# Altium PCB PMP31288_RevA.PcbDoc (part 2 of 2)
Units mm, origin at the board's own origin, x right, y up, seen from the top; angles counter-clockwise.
Board outline 73.66 x 62.23 mm, 2 copper layers (Top Layer, Bottom Layer), stack 1.575 mm thick; 96 components, 44 nets, 195 pads, 25 vias.
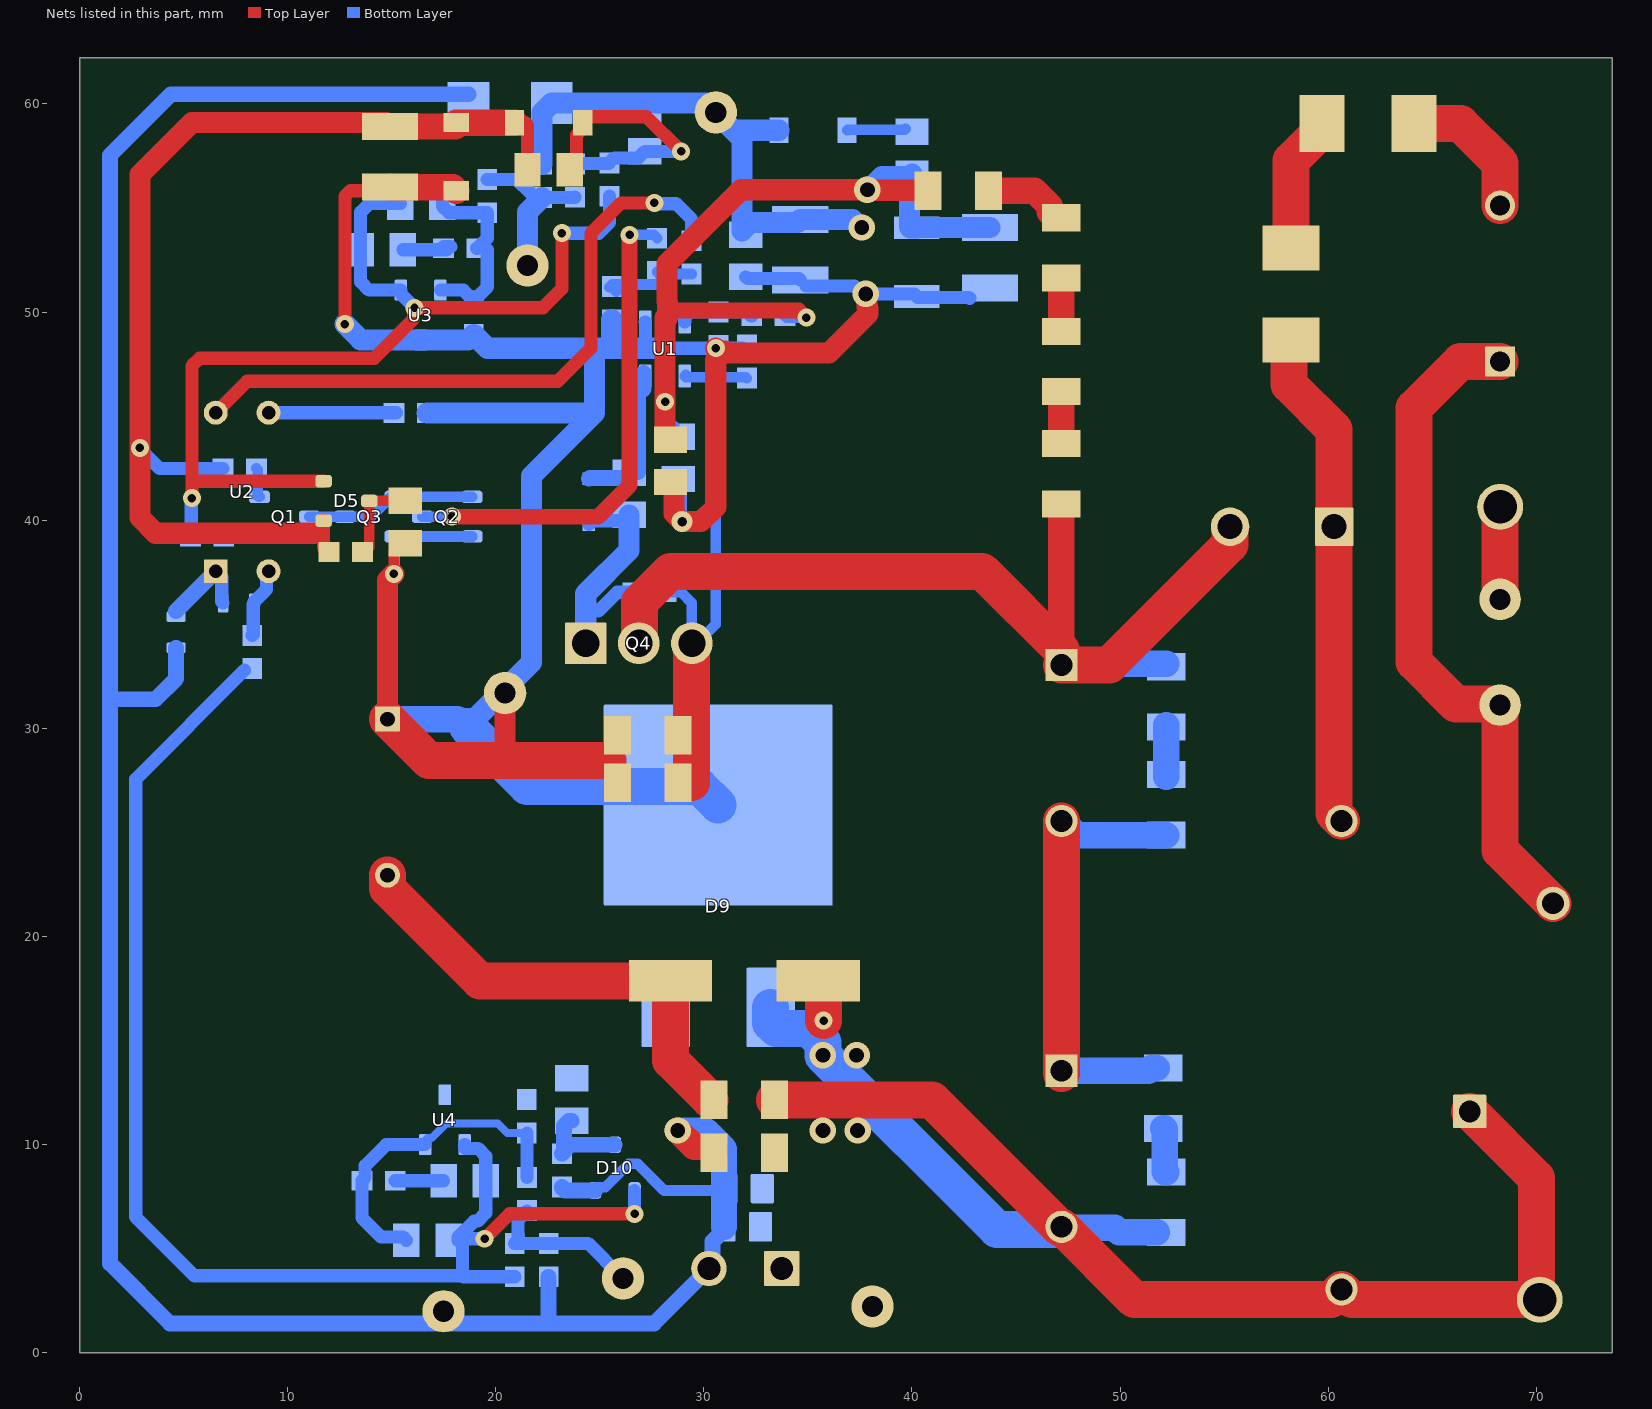
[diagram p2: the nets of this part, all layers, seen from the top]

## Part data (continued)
TP1 TP2 TP4 TP5 TP6: library part CMP-0055137-2, "Test Point, Miniature, Red, TH", Color=Red, Manufacturer="Keystone Electronics", Supplier Part Number 1=36-5000-ND
TP3: library part CMP-0055157-2, "Test Point, Multipurpose, Brown, TH", Color=Brown, Manufacturer="Keystone Electronics", Supplier Part Number 1=36-5125-ND
TP7: library part CMP-0055156-2, "Test Point, Multipurpose, Blue, TH", Color=Blue, Manufacturer="Keystone Electronics", Supplier Part Number 1=36-5127-ND
TP8: library part CMP-0055138-2, "Test Point, Miniature, Black, TH", Color=Black, Manufacturer="Keystone Electronics", Supplier Part Number 1=36-5001-ND
U1: library part CMP-0001574-1, "Continuous Conduction Mode (CCM) Secondary Side Regulated (SSR) Current-Mode Offline Flyback Controller", Manufacturer="Texas Instruments", Max Supply Voltage=29.7V, Min Supply Voltage=8V, Nominal Supply Current=1.8-2mA, Operating Temperature Range="-40°C to +125°C"
U2: library part CMP-0006173-3, "Optocoupler, 5 kV, 80-160% CTR, TH", Manufacturer="Fairchild Semiconductor", Supplier Part Number 1=FOD817A-ND, Voltage_Isolation_Vrms=5kV
U3 U4: library part CMP-0033157-1, "Adjustable Precision Shunt Regulator, 34 ppm / degC, 100 mA, -40 to 125 degC, 3-pin SOT-23 (DBZ), Green (RoHS & no Sb/Br)", Manufacturer="Texas Instruments", Rating=Catalog, Temp Coeff(Max)(ppm/ degree C)=92, Temp Coeff(Typ)(ppm/ degree C)=34
XF1: library part CMP-0003627-1, "Fuse Holder, TR5, TH", Manufacturer=Littelfuse, Supplier Part Number 1=WK6235-ND

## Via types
v1: diameter 0.864, hole 0.406, Top Layer to Bottom Layer, 14 vias
v2: diameter 1.27, hole 0.711, Top Layer to Bottom Layer, 8 vias
v3: diameter 0.864, hole 0.406, Top Layer to Bottom Layer, tented bottom, 2 vias
v4: diameter 1.016, hole 0.457, Top Layer to Bottom Layer, 1 vias

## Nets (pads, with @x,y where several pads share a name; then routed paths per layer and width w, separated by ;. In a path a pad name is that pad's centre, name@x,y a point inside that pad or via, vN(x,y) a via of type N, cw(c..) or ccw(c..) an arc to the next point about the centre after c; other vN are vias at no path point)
CS: Q4.3 R14.2 R27.2 R28.1 R31.2 | length 22
  Top Layer w1.778: 29.414,27.385 29.414,34.075 Q4.3@29.424,34.085
  Bottom Layer w0.508: R27.2@28.185,36.535 28.908,36.535 29.424,36.019 Q4.3@29.424,34.085 29.653,34.085 30.574,35.006 R14.2@30.574,45.398
DRV: D6.1 R26.2 U1.6 | length 6.9
  Bottom Layer w0.762: D6.1@24.476,41.992 24.514,42.029 26.154,42.029 R26.2@26.408,42.283 ; R26.2@26.849,42.309 26.849,46.063 27.103,46.317 U1.6@27.103,47.079
EA1: C14.2 C19.2 D10.1 R11.1 R34.1 U4.1 | length 65.8
  Top Layer w0.635: v1(19.467,5.469) 20.665,6.667 v3(26.67,6.667)
  Bottom Layer w0.635: R11.1@7.923,32.783 2.699,27.559 2.699,6.509 5.521,3.687 18.407,3.687 ; U4.1@18.506,9.992 18.506,9.827 18.524,9.81 19.15,9.81 19.522,9.438 C19.2@19.522,8.255 19.522,6.711 19.133,6.322 18.968,6.322 18.201,5.555 C14.2@18.201,5.39 ; v1(19.467,5.469) 18.28,5.469 C14.2@18.201,5.39 ; R34.1@20.908,3.645 18.449,3.645 18.407,3.687 ; D10.1@26.668,7.79 26.669,7.789 v3(26.67,6.667) v3(26.67,6.667) ; C14.2@18.201,5.39 18.407,5.184 18.407,3.687
FB: C9.1 R9.2 R21.2 U1.2 | length 7.1
  Bottom Layer w0.508: C9.1@25.465,51.193 25.597,51.325 28.134,51.325 U1.2@28.134,49.526 ; C9.1@25.575,51.228 25.575,51.203 C9.1@25.796,50.982 ; R21.2@27.753,51.946 27.753,51.921 28.229,51.445 ; R21.2@27.845,51.829 R9.2@29.408,51.829
NetC1_1: C1.1 C2.1 C6.1 C7.1 R1.2 R8.2 R12.2 U1.5 | length 42.1
  Top Layer w0.762: 28.253,50.078 34.548,50.078 34.898,49.729 v1(34.925,49.729)
  Top Layer w1.016: 28.134,49.729 v1(28.134,45.69) 28.134,43.994 28.261,43.867 C6.1@28.394,43.867 ; 28.253,49.729 28.253,50.078 28.253,50.478 28.228,50.502 28.228,52.322 31.786,55.88 v2(37.856,55.88) 37.881,55.855 40.753,55.855 R12.2@40.778,55.83
  Bottom Layer w0.508: U1.5@28.134,46.926 v1(28.134,45.69) 28.134,44.715 28.331,44.517 C7.1@28.57,44.517 ; R8.2@33.899,49.806 33.977,49.729 v1(34.925,49.729) ; v2(37.856,55.88) v2@37.856,55.891
  Bottom Layer w1.016: v2(37.856,55.88) 37.925,55.88 38.56,56.515 39.878,56.515 R1.2@40.005,56.642 ; R1.2@39.877,56.558 39.877,54.095 39.92,54.053 C2.1@40.234,54.053 40.239,54.058 43.751,54.058 C1.1@43.756,54.064
NetC3_1: C3.1 D3.1 D4.1 D5.2 R4.2 R15.2 R16.2 | length 54
  Top Layer w0.635: 11.256,39.37 11.646,39.759 11.646,39.957 11.663,39.975 D5.2@11.728,39.975 11.728,38.735 ccw(c11.993,38.735) R16.2@11.993,38.47 ; C3.1@14.735,59.105 C3.1@14.922,58.917 ; D3.1@20.905,59.105 21.339,59.105 cw(c21.339,58.917) 21.526,58.917 R4.2@21.526,56.832
  Top Layer w1.016: 11.256,39.37 3.651,39.37 2.897,40.125 v1(2.897,43.473) 2.897,56.603 5.399,59.105 C3.1@14.735,59.105
  Top Layer w1.27: C3.1@14.922,58.917 D4.1@18.063,58.917 ; D4.1@18.098,59.105 D3.1@20.905,59.105
  Bottom Layer w0.635: v1(2.897,43.473) 2.897,43.429 3.841,42.485 R15.2@6.896,42.485
NetC4_1: C4.1 C5.1 D1.2 D2.1 R2.2 R3.1 TP1.1 | length 25.7
  Bottom Layer w1.016: R2.2@22.225,57.099 22.225,59.578 D2.1@22.691,60.045 30.125,60.045 TP1.1@30.574,59.596 31.432,58.737 ; D1.2@33.605,58.737 31.432,58.737 ; v2(37.586,54.064) 37.517,54.064 37.137,54.443 34.631,54.443 C4.1@34.63,54.445 34.488,54.303 32.242,54.303 31.84,53.9 31.84,58.33 31.432,58.737
NetC8_1: C8.1 R13.1 R19.1 R24.2 U3.2 | length 9
  Bottom Layer w0.635: U3.2@17.342,51.056 18.438,51.056 R24.2@18.941,50.554 ; C8.1@17.438,55.379 C8.1@17.438,55.214 17.438,55.086 17.755,54.769 R13.1@19.589,54.769 19.589,53.543 19.114,53.069 R19.1@19.089,53.069 ; R24.2@18.941,50.529 R24.2@18.941,50.554 ; R19.1@19.589,52.995 19.589,51.201 R24.2@18.941,50.554
NetC8_2: C8.2 C11.2 D5.1 R7.1 R20.1 U3.1 | length 49.2
  Top Layer w0.635: v1(5.399,41.059) 5.399,41.875 ; D5.1@11.728,41.875 5.399,41.875 ; v1(23.177,53.789) 23.177,51.117 22.264,50.204 v1(16.094,50.204) 16.05,50.16 16.05,49.671 14.163,47.784 5.771,47.784 5.399,47.412 5.399,41.875
  Bottom Layer w0.635: R20.1@5.328,39.217 5.363,39.252 5.363,41.024 v1(5.399,41.059) ; C8.2@15.406,55.214 13.924,55.214 13.506,54.796 C11.2@13.506,52.995 13.506,51.459 13.908,51.056 U3.1@15.442,51.056 15.442,50.891 16.094,50.239 v1(16.094,50.204) ; v1(23.177,53.789) 24.951,53.789 25.465,54.303 R7.1@25.465,55.569
NetC10_1: C10.1 R14.1 U1.4 | length 3
  Bottom Layer w0.508: U1.4@29.084,46.926 29.084,46.921 29.13,46.875 32.017,46.875 C10.1@32.067,46.825 ; U1.4@29.128,46.992 U1.4@29.13,46.991
NetC11_1: C11.1 R19.2 | length 2.5
  Bottom Layer w0.635: C11.1@15.538,52.995 R19.2@17.638,52.995 ; R19.2@17.489,53.143 R19.2@17.84,53.143
NetC12_1: C12.1 D5.3 R16.1 | length 4.4
  Top Layer w0.508: R16.1@13.593,38.47 ccw(c13.593,38.806) 13.928,38.806 D5.3@13.928,40.925 C12.1@15.65,40.925
  Top Layer w1.016: C12.1@15.65,40.925 C12.1@15.65,40.927
NetC13_1: C13.1 L1.2 Q4.2 R25.1 R32.2 | length 48.6
  Top Layer w1.27: C13.1@47.184,33.04 47.184,33.735 R25.1@47.184,40.778
  Top Layer w1.778: Q4.2@26.874,34.085 26.916,34.128 26.916,36.067 28.394,37.545 43.374,37.545 C13.1@47.184,33.735 ; C13.1@47.184,33.04 49.484,33.04 55.271,38.827 55.271,39.674 L1.2@55.285,39.688
  Bottom Layer w1.27: C13.1@47.184,33.04 47.252,33.108 R32.2@52.229,33.108
NetC13_2: C13.2 C20.1 R33.1 R41.2 | length 22.1
  Top Layer w1.778: C20.1@47.184,13.415 C20.1@47.184,13.545 C13.2@47.184,25.54
  Bottom Layer w1.27: C13.2@47.184,25.54 47.259,25.54 47.939,24.86 R33.1@52.229,24.86 ; C20.1@47.197,13.558 C20.1@47.184,13.545 51.348,13.545 51.478,13.674 R41.2@51.752,13.674
NetC14_1: C14.1 R35.1 R40.1 R43.2 U4.2 | length 16.2
  Bottom Layer w0.381: U4.2@16.606,9.992 16.606,10.192 16.716,10.302 16.916,10.302 17.625,11.011 20.094,11.011 20.551,10.553 R43.2@21.497,10.553
  Bottom Layer w0.635: C14.1@15.7,5.402 15.543,5.559 14.484,5.559 13.571,6.472 R40.1@13.571,8.255 13.723,8.407 13.723,8.98 14.735,9.992 U4.2@16.606,9.992 ; R43.2@21.497,10.553 21.497,8.424 R35.1@21.501,8.42
NetC15_1: C15.1 D8.1 L1.1 | length 24.2
  Top Layer w1.778: D8.1@58.219,48.662 58.114,48.556 58.114,46.521 60.285,44.35 L1.1@60.285,39.688 60.285,25.895 C15.1@60.642,25.538
NetC19_1: C19.1 R40.2 | length 2.3
  Bottom Layer w0.635: R40.2@15.171,8.255 C19.1@17.49,8.255
NetC21_1: C21.1 D10.3 R36.1 | length 4.4
  Bottom Layer w0.762: R36.1@23.177,9.552 23.272,9.646 R36.1@23.272,9.671 ; C21.1@23.652,11.141 23.526,11.141 23.272,10.887 R36.1@23.272,9.671 ; D10.3@25.717,9.99 23.591,9.99 R36.1@23.272,9.671
NetD1_1: D1.1 R1.1 | length 2.8
  Bottom Layer w0.508: D1.1@36.88,58.737 36.912,58.769 39.656,58.769 R1.1@39.688,58.801
NetD3_2: D3.2 R3.2 R4.1 R5.2 R7.2 | length 13.6
  Top Layer w0.635: R4.1@23.558,56.832 23.876,57.15 23.876,58.498 24.04,58.663 24.04,58.812 24.105,58.877 24.255,58.877 24.255,59.323 24.32,59.388 27.242,59.388 v1(28.908,57.721)
  Bottom Layer w0.635: R5.2@23.812,57.121 23.836,57.145 25.441,57.145 R7.2@25.465,57.169 25.465,57.194 25.623,57.351 25.648,57.351 25.7,57.404 26.849,57.404 R3.2@27.166,57.721 v1(28.908,57.721)
NetD6_2: D6.2 Q4.1 R26.1 R27.1 | length 11.8
  Bottom Layer w0.635: 24.324,35.64 24.939,35.64 25.834,36.535 R27.1@26.584,36.535 ; 24.324,36.462 24.397,36.535 ; D6.2@24.476,39.792 24.656,39.971 26.128,39.971 R26.1@26.408,40.251
  Bottom Layer w1.016: Q4.1@24.324,34.085 24.324,35.64 24.324,36.462 ; 24.397,36.535 26.408,38.546 R26.1@26.408,40.251
NetD7_1: D7.1 D8.2 | length 6.6
  Top Layer w1.778: D8.2@58.219,53.082 58.219,57.28 59.702,58.763 D7.1@59.702,59.055
NetD7_2: D7.2 R29.2 | length 7
  Top Layer w1.778: D7.2@64.123,59.055 66.358,59.055 68.263,57.15 R29.2@68.263,55.125
NetQ1_1: Q1.1 R20.2 | length 1.7
  Bottom Layer w0.508: R20.2@6.928,39.217 Q1.1@8.646,39.217
NetQ1_2: Q1.2 R15.1 | length 1.4
  Bottom Layer w0.508: R15.1@8.496,42.485 8.571,42.41 8.571,41.163 8.617,41.117 Q1.2@8.646,41.117
NetQ1_3: Q1.3 Q2.1 Q3.1 Q3.3 | length 8.2
  Bottom Layer w0.508: Q1.3@11.046,40.167 Q3.3@12.75,40.167 14.012,40.167 14.904,41.059 14.904,41.071 14.95,41.117 Q3.1@15.15,41.117 Q2.1@18.866,41.117
NetQ2_3: Q2.3 R21.1 | length 24
  Top Layer w0.762: v1@17.886,40.164 24.922,40.164 26.434,41.675 v1(26.434,53.706)
  Bottom Layer w0.508: Q2.3@16.466,40.167 v1(17.886,40.167) ; v1(26.434,53.706) 27.593,53.706 R21.1@27.753,53.546
NetR2_1: R2.1 R5.1 R13.2 TP2.1 | length 7.5
  Bottom Layer w0.635: R13.2@19.589,56.369 21.016,56.369 21.704,55.681 ; R2.1@22.225,55.499 22.236,55.51 23.801,55.51 R5.1@23.812,55.521
  Bottom Layer w1.016: TP2.1@21.526,52.236 21.526,54.8 R2.1@22.225,55.499
NetR6_1: R6.1 R10.2 U2.1 | length 4.4
  Bottom Layer w0.635: U2.1@6.544,37.545 6.829,37.259 6.829,36.086 R10.2@6.896,36.019
  Bottom Layer w0.762: 4.639,35.64 U2.1@6.544,37.545
NetR8_1: R8.1 R22.2 U1.3 | length 3.6
  Bottom Layer w0.635: U1.3@29.084,49.526 29.084,49.741 29.348,50.006 30.695,50.006 R22.2@30.697,50.003 32.077,50.003 32.274,49.806 R8.1@32.299,49.806
NetR9_1: R9.1 U2.4 | length 31.8
  Top Layer w0.635: U2.4@6.544,45.165 8.052,46.672 22.982,46.672 24.573,48.263 24.573,53.789 26.029,55.245 v3(27.622,55.245)
  Bottom Layer w0.635: U2.4@6.544,45.165 U2.4@6.544,45.304 ; v3(27.622,55.245) 27.666,55.201 28.667,55.201 29.408,54.46 R9.1@29.408,53.429
NetR10_1: R10.1 R11.2 U2.2 | length 3.4
  Bottom Layer w0.635: R11.2@8.303,34.465 8.35,34.512 8.35,35.972 R10.1@8.396,36.019 8.396,36.084 8.985,36.673 8.985,37.446 U2.2@9.084,37.545
NetR12_1: R12.1 R17.2 | length 4.2
  Top Layer w1.27: R12.1@43.677,55.83 45.885,55.83 46.629,55.086 46.629,54.811 46.909,54.532 R17.2@47.184,54.532
NetR17_1: R17.1 R23.2 | length 2.6
  Top Layer w1.27: R23.2@47.184,49.075 R17.1@47.184,51.632
NetR18_2: R18.2 U2.3 | length 6.1
  Bottom Layer w0.635: U2.3@9.084,45.165 R18.2@15.221,45.165
NetR23_1: R23.1 R25.2 | length 2.5
  Top Layer w1.27: R25.2@47.184,43.677 R23.1@47.184,46.175
NetR29_1: R29.1 R37.2 XF1.1 | length 32.8
  Top Layer w1.778: R29.1@68.263,47.625 66.358,47.625 64.123,45.39 64.123,33.181 66.146,31.157 68.22,31.157 XF1.1@68.263,31.115 68.263,24.13 R37.2@70.802,21.59
NetR30_1: R30.1 R34.2 R35.2 TP6.1 | length 8
  Bottom Layer w0.635: R35.2@21.683,6.638 21.658,6.638 21.501,6.795 21.065,6.36 21.065,5.402 R34.2@20.908,5.245 R30.1@22.543,5.245 24.439,5.245 26.039,3.644 26.039,3.568 TP6.1@26.116,3.568
NetR32_1: R32.1 R33.2 | length 2.5
  Bottom Layer w1.27: R33.2@52.229,27.674 R32.1@52.229,30.137
NetR41_1: R41.1 R42.2 | length 2.2
  Bottom Layer w1.27: R41.1@52.07,10.774 52.134,10.774 52.149,10.759 52.149,8.69 52.164,8.675 R42.2@52.229,8.675
NetTP3_1: TP3.1 XF1.2 | length 4.4
  Top Layer w1.778: XF1.2@68.263,36.195 TP3.1@68.263,40.64
PGND: C15.2 C16.2 C17.2 C18.2 C20.2 C21.2 D9.1 D9.3 J1.1 R37.1 R38.1 R39.1 R42.1 R43.1 TP7.1 TP8.1 U4.3 | length 77.5
  Top Layer w1.778: C17.2@33.394,12.145 40.954,12.145 C20.2@47.119,5.98 ; C18.2@35.494,17.86 35.643,17.86 35.754,17.749 v1(35.754,15.955) ; C20.2@47.184,6.045 50.688,2.54 60.145,2.54 C15.2@60.642,3.037 61.14,2.54 TP7.1@70.168,2.54 70.168,2.657 70.009,2.816 70.009,8.384 R37.1@66.802,11.59
  Bottom Layer w1.27: C20.2@47.184,6.045 47.237,5.991 49.748,5.991 49.964,5.775 R42.1@51.752,5.775
  Bottom Layer w1.778: D9.1@33.214,16.59 33.214,15.845 33.485,15.574 35.045,15.574 35.719,14.9 v2(35.719,14.287) 44.092,5.915 C20.2@47.184,5.915
  other v2: 35.719,10.672 37.386,10.672 37.342,14.287
SN: C1.2 C2.2 C3.2 C4.2 C5.2 C6.2 C7.2 C9.2 C10.2 C12.2 D4.2 D9.4 L2.1 Q2.2 Q3.2 R18.1 R22.1 R24.1 R28.2 R31.1 TP4.1 U1.1 U3.3 | length 142.9
  Top Layer w0.508: v1(15.1,37.418) 15.104,37.422 15.104,38.514 15.485,38.895 C12.2@15.65,38.895
  Top Layer w0.635: v1(12.75,49.421) 12.75,55.563 13.017,55.829 14.734,55.829 C3.2@14.922,56.018
  Top Layer w1.016: L2.1@14.799,30.44 14.799,37.117 v1(15.1,37.418) ; TP4.1@20.45,31.693 20.45,28.587 20.585,28.452 ; C6.2@28.394,41.835 28.433,41.835 28.56,41.708 28.56,40.321 v4(28.951,39.93) 29.864,39.93 30.574,40.64 30.574,47.696 31.001,48.124 ; v1(30.574,48.263) 30.806,48.031 36.007,48.031 37.881,49.905 37.881,50.204 37.831,50.254 37.831,50.823 v2(37.782,50.872)
  Top Layer w1.27: C3.2@14.922,56.018 14.938,56.002 17.925,56.002 D4.2@18.098,55.83
  Top Layer w1.778: L2.1@14.799,30.44 16.787,28.452 20.585,28.452 25.394,28.452
  Bottom Layer w0.508: v1(15.1,37.418) 15.15,37.468 Q3.2@15.15,39.217 Q2.2@18.866,39.217
  Bottom Layer w0.635: U1.1@27.184,49.526 27.201,49.508 27.201,48.618 27.556,48.263 v1(30.574,48.263) C10.2@31.84,48.263 ; C7.2@28.773,41.978 28.879,41.872 28.879,40.002 v4(28.951,39.93) ; C5.2@32.017,51.69 32.09,51.618 34.557,51.618 C4.2@34.63,51.545 ; C4.2@34.925,51.259 37.224,51.259 ; v2(37.782,50.872) 40.114,50.872 40.279,50.707 42.728,50.707 C1.2@42.774,50.661
  Bottom Layer w1.016: v1(12.75,49.421) 13.515,48.656 U3.3@16.392,48.656 18.668,48.656 R24.1@18.941,48.929 19.606,48.263 24.746,48.263 ; R18.1@16.707,45.145 24.746,45.145 ; 18.152,30.44 18.517,30.075 18.63,30.075 21.716,33.161 21.716,42.114 24.746,45.145 ; C9.2@25.575,49.628 25.575,48.263 ; 27.556,48.263 25.575,48.263 ; 24.746,45.145 24.746,48.263 ; 24.746,48.263 25.575,48.263
  Bottom Layer w1.27: L2.1@14.799,30.44 18.152,30.44
  Bottom Layer w1.778: 18.63,30.075 21.501,27.205 29.794,27.205 D9.4@30.689,26.31
Vout: C16.1 C17.1 C18.1 D2.2 D10.2 J1.2 L2.2 R6.2 R30.2 R36.2 R38.2 R39.2 TP5.1 | length 152.6
  Top Layer w1.27: v2(28.749,10.672) 29.544,9.877 30.479,9.877 30.494,9.862 C16.1@30.494,9.605
  Top Layer w1.778: L2.2@14.799,22.94 14.799,22.305 19.244,17.86 C18.1@28.394,17.86 28.394,14.042 C17.1@30.291,12.145
  Bottom Layer w0.508: D10.2@24.768,7.79 24.768,7.89 24.814,7.936 25.258,7.936 26.389,9.067 26.81,9.067 28.087,7.79 R38.2@30.926,7.79
  Bottom Layer w0.762: R6.2@4.639,33.865 4.639,32.385 3.646,31.392 1.46,31.392 ; D2.2@18.691,60.464 4.396,60.464 1.46,57.529 1.46,31.392 ; R30.2@22.543,3.645 22.543,1.397 ; R36.2@23.177,7.952 23.177,7.927 23.314,7.79 D10.2@24.768,7.79 ; R39.2@30.968,6.045 30.968,5.894 30.423,5.349 30.423,4.219 J1.2@30.244,4.04 27.601,1.397 22.543,1.397 ; 1.46,31.392 1.46,4.284 4.348,1.397 17.493,1.397 22.543,1.397
  Bottom Layer w1.27: v2(28.749,10.672) 30.076,10.672 30.968,9.781 30.968,7.79 R39.2@30.968,6.045

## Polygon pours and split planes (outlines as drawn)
Vout on Top Layer "TOP_LAYER_VOUT_P003" (solid, pour order 3): 11.424,21.67 11.424,22.305 cw(c13.329,22.305) 12.183,23.826 16.916,23.826 cw(c17.085,23.014) 17.774,22.55 17.774,22.021 ccw(c20.314,22.021) 20.314,19.481 29.612,19.481 cw(c29.612,18.62) 30.474,18.62 30.474,1.985 cw(c29.204,1.984) 29.204,0.715 12.694,0.715 cw(c12.694,1.985) 11.424,1.985
SN on Top Layer "TOP_LAYER_SN_P013" (solid, pour order 13): 13.593,31.009 cw(c14.489,30.796) 14.701,31.693 26.13,31.693 cw(c25.972,30.995) 26.67,30.837 26.67,26.75 cw(c26.13,26.75) 25.607,26.885 14.95,26.885 cw(c17.799,32.016) 13.63,27.885
PGND on Top Layer "TOP_LAYER_PGND_P002" (solid, pour order 2): 32.544,18.489 32.544,18.689 cw(c33.614,18.689) 33.614,19.759 43.139,19.759 cw(c43.139,18.489) 44.409,18.489 44.409,12.139 ccw(c46.314,12.139) 46.314,10.234 53.299,10.234 cw(c53.299,8.329) 55.204,8.329 55.204,1.979 cw(c53.934,1.979) 53.934,0.709 32.979,0.709 cw(c32.979,1.344) 32.344,1.344
NetC13_1 on Top Layer "TOP_LAYER_NETC13_1_P000" (solid, pour order 0): 26.029,37.545 cw(c26.968,37.545) 26.968,38.484 55.239,38.484 cw(c55.153,37.233) 56.404,37.147 56.404,30.455 cw(c55.239,30.455) 55.239,29.29 39.999,29.29 cw(c39.999,30.56) 38.729,30.56 38.729,33.527 ccw(c36.189,33.527) 36.189,36.067 26.871,36.067 cw(c26.871,36.91) 26.029,36.91
PGND on Bottom Layer "BOTTOM_LAYER_PGND_P011" (solid, remove dead copper, pour order 11): 1.069,59.562 cw(c2.974,59.562) 2.974,61.467 48.694,61.467 cw(c48.694,60.197) 49.964,60.197 49.964,2.678 cw(c48.059,2.678) 48.059,0.773 3.467,0.773 cw(c3.467,3.313) 0.927,3.313 0.927,3.823
SN on Bottom Layer "BOTTOM_LAYER_SN_P012" (solid, pour order 12): 31.001,51.686 31.001,52.031 cw(c31.292,52.031) 31.292,52.322 44.98,52.322 cw(c44.98,51.946) 45.356,51.946 45.356,50.432 cw(c45.188,50.432) 45.188,50.264 37.478,50.264 cw(c37.478,50.661) 37.081,50.661 ccw(c36.85,50.661) 36.85,50.891 31.369,50.891 cw(c31.369,51.259) 31.001,51.259 31.001,52.031 cw(c31.292,52.031) 31.292,52.322
SN on Bottom Layer "BOTTOM_LAYER_SN_P004" (solid, pour order 4): 36.824,22.105 cw(c35.754,22.105) 35.754,21.035 25.394,21.035 cw(c25.394,21.67) 24.759,21.67 24.759,24.905 ccw(c24.124,24.905) 24.124,25.54 18.349,25.54 cw(c18.349,26.75) 17.139,26.75 17.139,30.56 cw(c17.774,30.56) 17.774,31.195 36.189,31.195 cw(c36.189,30.56) 36.824,30.56

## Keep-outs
Keep-Out Layer:
  text ".Layer_Name" at 14.656,-21.806 h1.52

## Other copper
Top Layer:
  text ".Layer_Name" at 14.656,-21.806 h1.52
Bottom Layer:
  text ".Layer_Name" at 14.656,-21.806 h1.52

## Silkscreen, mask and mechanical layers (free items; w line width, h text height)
Top Overlay:
  text "'.PRJ_Number'.PCB_Rev" at 41.751,59.055 h2.75
  text "IN" at 65.084,40.077 h0.9
  text "SN" at 17.074,31.577 h0.9
  text "VOUT" at 11.768,1.583 h1
  text "PGND" at 73.206,1.287 h0.9 r90
  text ".Layer_Name" at 14.656,-21.806 h1.52
Bottom Overlay:
  text ".Layer_Name" at 14.656,-21.806 h1.52
Top Paste:
  text ".Layer_Name" at 14.656,-21.806 h1.52
Bottom Paste:
  text ".Layer_Name" at 14.656,-21.806 h1.52
Top Solder:
  text ".Layer_Name" at 14.656,-21.806 h1.52
  text ".Layer_Name" at 14.656,-21.806 h1.52
Bottom Solder:
  text ".Layer_Name" at 14.656,-21.806 h1.52
Drill Guide:
  text ".Layer_Name" at 14.656,-21.806 h1.52
M1 Board Outline:
  the board outline again, w0.254
  text ".Layer_Name" at 14.656,-21.806 h1.52
M2 Board Dimensions:
  rectangle: 3.175,-10.16 12.7,-6.985
  rectangle: 0,-6.985 3.175,-3.81
  lines w0.178: 0,-6.985 25.4,-6.985 ; 3.175,-10.16 3.175,-3.81 ; 6.35,-10.16 6.35,-3.81 ; 12.7,-10.16 12.7,-3.81 ; 19.05,-10.16 19.05,-3.81 ; 0,-10.16 0,-3.81 25.4,-3.81 25.4,-10.16 0,-10.16
  text ".Layer_Name" at 14.656,-21.806 h1.52
M3 3D STEP Top:
  text ".Layer_Name" at 14.656,-21.806 h1.52
M4 3D STEP Bottom:
  text ".Layer_Name" at 14.656,-21.806 h1.52
M5 Assembly Top:
  lines w0.254: -7.417,-23.626 160.223,-23.626 ; -7.417,-18.462 160.274,-18.462 ; -7.417,-13.297 -7.417,-28.791 94.31,-28.791 160.274,-28.791 160.274,-13.297 -7.404,-13.297 -7.404,-28.791 32.614,-28.791 ; 55.194,-28.791 55.194,-13.297 ; 87.376,-18.462 87.376,-13.297 ; 108.712,-18.462 108.712,-13.297 ; 124.511,-28.956 124.511,-23.804
  text "COMPONENTS MARKED 'DNP' SHOULD NOT BE POPULATED." at 29.299,-8.09 h1.52
  text "ASSEMBLY VARIANT:" at 29.286,-11.024 h1.52
  text ".VariantName" at 55.601,-11.024 h1.52
  text "PCB VIEWED FROM TOP SIDE" at -5.804,-16.654 h1.52
  text "BOARD #:" at 57.099,-16.654 h1.52
  text ".PRJ_Number" at 70.955,-16.654 h1.52
  text "REV:" at 92.405,-16.654 h1.52
  text ".PCB_Rev" at 99.809,-16.654 h1.52
  text "SVN REV:" at 113.69,-16.654 h1.52
  text ".VersionControl_RevNumber" at 126.543,-16.654 h1.52
  text "PLOT NAME =" at -5.804,-27.034 h1.52
  text ".plot_File_Name" at 14.656,-27.034 h1.52
  text "GENERATED    :" at 57.15,-27.034 h1.52
  text ".Print_Date" at 79.235,-27.034 h1.52
  text ".Print_Time" at 97.752,-27.034 h1.52
  text "TEXAS INSTRUMENTS" at 129.87,-27.034 h1.52
M6 Assembly Bottom:
  lines w0.254: -7.429,-18.474 160.261,-18.474 ; -7.379,-23.639 160.261,-23.639 ; 28.334,-28.969 28.334,-23.817 ; 44.133,-18.474 44.133,-13.31 ; 65.468,-18.474 65.468,-13.31 ; 97.65,-28.804 97.65,-13.31 ; 120.231,-28.804 160.249,-28.804 160.249,-13.31 -7.429,-13.31 -7.429,-28.804 58.534,-28.804 160.261,-28.804 160.261,-13.31
  text "COMPONENTS MARKED 'DNP' SHOULD NOT BE POPULATED." at 154.991,-8.077 h1.52
  text ".VariantName" at 128.473,-11.024 h1.52
  text "ASSEMBLY VARIANT:" at 154.864,-11.024 h1.52
  text ".VersionControl_RevNumber" at 26.302,-16.667 h1.52
  text "SVN REV:" at 39.154,-16.667 h1.52
  text ".PCB_Rev" at 53.035,-16.667 h1.52
  text "REV:" at 60.439,-16.667 h1.52
  text ".PRJ_Number" at 81.89,-16.667 h1.52
  text "BOARD #:" at 95.745,-16.667 h1.52
  text "PCB VIEWED FROM BOTTOM SIDE" at 158.648,-16.667 h1.52
  text "TEXAS INSTRUMENTS" at 22.974,-27.047 h1.52
  text ".Print_Time" at 55.093,-27.047 h1.52
  text ".Print_Date" at 73.609,-27.047 h1.52
  text "GENERATED    :" at 95.694,-27.047 h1.52
  text ".plot_File_Name" at 138.189,-27.047 h1.52
  text "PLOT NAME =" at 158.648,-27.047 h1.52
M9 Title Sheet:
  drawing of 63 lines, arcs and shapes, not listed
  text "1" at 35.293,466.75 h1.78
  text "2" at 136.766,466.75 h1.78
  text "3" at 238.239,466.75 h1.78
  text "4" at 339.865,466.75 h1.78
  text "5" at 441.423,466.75 h1.78
  text "6" at 542.98,466.75 h1.78
  text "7" at 644.623,466.75 h1.78
  text "8" at 746.096,466.75 h1.78
  text "A" at -11.874,405.841 h1.78
  text "A" at 793.305,405.841 h1.78
  text "B" at -11.874,278.841 h1.78
  text "B" at 793.305,278.841 h1.78
  text "C" at -11.874,151.841 h1.78
  text "C" at 793.305,151.841 h1.78
  text "D" at -11.874,24.841 h1.78
  text "D" at 793.305,24.841 h1.78
  text "PROJECT TITLE:" at 714.947,6.823 h1.14
  text ".PRJ_Title" at 716.216,3.436 h1.78
  text "DESIGNED FOR:" at 714.947,-0.823 h1.14
  text ".PRJ_Customer" at 716.216,-4.379 h1.78
  text "FILE NAME:" at 714.947,-8.443 h1.14
  text ".PCB_File_Name_No_Path" at 716.216,-11.491 h1.78
  text "Texas Instruments (TI) and/or its licensors do not warrant the accuracy or completeness of this specification" at 588.721,-15.601 h1.14
  text "ENGINEER:" at 714.947,-15.809 h1.14
  text "LAYOUT BY:" at 753.173,-15.809 h1.14
  text "or any information contained therein. TI and/or its licensors do not warrant that this design will meet" at 587.579,-18.463 h1.14
  text ".PRJ_Engineer" at 716.216,-19.746 h1.78
  text ".PCB_Layout" at 754.456,-19.746 h1.78
  text "the specifications, will be suitable for your application or fit for any particular purpose, or will operate in" at 587.579,-21.325 h1.14
  text ".Layer_Name" at 14.656,-21.806 h1.52
  text "ALTIUM DESIGNER VERSION:" at 753.173,-23.683 h1.14
  text "an implementation. TI and/or its licensors do not warrant that the design is production worthy. You should" at 587.579,-24.187 h1.14
  text "completely validate and test your design implementation to confirm the system functionality for your application." at 588.721,-27.048 h1.14
  text ".print_Scale" at 716.216,-27.069 h1.78
  text ".Application_BuildNumber" at 754.456,-27.069 h1.78
  text "1" at 35.293,-33.503 h1.78
  text "2" at 136.766,-33.503 h1.78
  text "3" at 238.239,-33.503 h1.78
  text "4" at 339.865,-33.503 h1.78
  text "5" at 441.423,-33.503 h1.78
  text "6" at 542.98,-33.503 h1.78
  text "7" at 644.623,-33.503 h1.78
  text "8" at 746.096,-33.503 h1.78
M10 Fab Notes:
  text ".Layer_Name" at 14.656,-21.806 h1.52
M11 Gerber Information:
  lines w0.254: -7.417,-23.626 160.223,-23.626 ; -7.417,-18.462 160.274,-18.462 ; -7.417,-13.297 -7.417,-28.791 94.31,-28.791 160.274,-28.791 160.274,-13.297 -7.404,-13.297 -7.404,-28.791 32.614,-28.791 ; 55.194,-28.791 55.194,-13.297 ; 87.376,-18.462 87.376,-13.297 ; 108.712,-18.462 108.712,-13.297 ; 124.511,-28.956 124.511,-23.804
  text "ALL ARTWORK VIEWED FROM TOP SIDE" at -5.804,-16.654 h1.52
  text "BOARD #:" at 57.099,-16.654 h1.52
  text ".PRJ_Number" at 70.955,-16.654 h1.52
  text "REV:" at 92.405,-16.654 h1.52
  text ".PCB_Rev" at 99.809,-16.654 h1.52
  text "SVN REV:" at 113.69,-16.654 h1.52
  text ".VersionControl_RevNumber" at 126.543,-16.654 h1.52
  text "LAYER NAME =" at -5.804,-21.806 h1.52
  text "PLOT NAME =" at -5.804,-27.034 h1.52
  text ".plot_File_Name" at 14.656,-27.034 h1.52
  text "GENERATED    :" at 57.15,-27.034 h1.52
  text ".Print_Date" at 79.235,-27.034 h1.52
  text ".Print_Time" at 97.752,-27.034 h1.52
  text "TEXAS INSTRUMENTS" at 129.87,-27.034 h1.52
M12 Stackup:
  drawing of 191 lines, arcs and shapes, not listed
  text "Layer" at 674.469,457.523 h1.52
  text "Name" at 684.88,457.523 h1.52
  text "Material" at 708.496,457.523 h1.52
  text "Thickness" at 730.334,457.523 h1.52
  text "Constant" at 746.84,457.523 h1.52
  text "Board Layer Stack" at 761.314,457.523 h1.52
  text "Top Overlay" at 684.88,454.475 h1.52
  text "Top Solder" at 684.88,451.427 h1.52
  text "Solder Resist" at 708.496,451.427 h1.52
  text "0.40mil" at 730.334,451.427 h1.52
  text "3.5" at 746.84,451.427 h1.52
  text "1" at 674.469,448.379 h1.52
  text "Top Layer" at 684.88,448.379 h1.52
  text "1.40mil" at 730.334,448.379 h1.52
  text "Dielectric1" at 684.88,445.331 h1.52
  text "FR-4 High Tg" at 708.496,445.331 h1.52
  text "59.20mil" at 730.334,445.331 h1.52
  text "4.8" at 746.84,445.331 h1.52
  text "2" at 674.469,442.283 h1.52
  text "Bottom Layer" at 684.88,442.283 h1.52
  text "1.40mil" at 730.334,442.283 h1.52
  text "Bottom Solder" at 684.88,439.235 h1.52
  text "Solder Resist" at 708.496,439.235 h1.52
  text "0.40mil" at 730.334,439.235 h1.52
  text "3.5" at 746.84,439.235 h1.52
  text "Bottom Overlay" at 684.88,436.187 h1.52
  text ".Layer_Name" at 14.656,-21.806 h1.52
M13 Component Bodies Top:
  text ".Layer_Name" at 14.656,-21.806 h1.52
M14 Component Bodies Bottom:
  text ".Layer_Name" at 14.656,-21.806 h1.52
M15 Courtyards Top:
  text ".Layer_Name" at 14.656,-21.806 h1.52
M16 Courtyards Bottom:
  text ".Layer_Name" at 14.656,-21.806 h1.52
Drill Drawing:
  text ".Layer_Name" at 14.656,-21.806 h1.52
M17 Embedded Cavity:
  text ".Layer_Name" at 14.656,-21.806 h1.52
M18 Embedded Assembly:
  text ".Layer_Name" at 14.656,-21.806 h1.52
M19 Embedded Keepout:
  text ".Layer_Name" at 14.91,-21.552 h1.52

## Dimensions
0,0 to 73.66,0 on M2 Board Dimensions
0,0 to 0,62.23 on M2 Board Dimensions
0,-10.16 to 25.4,-10.16 on M2 Board Dimensions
